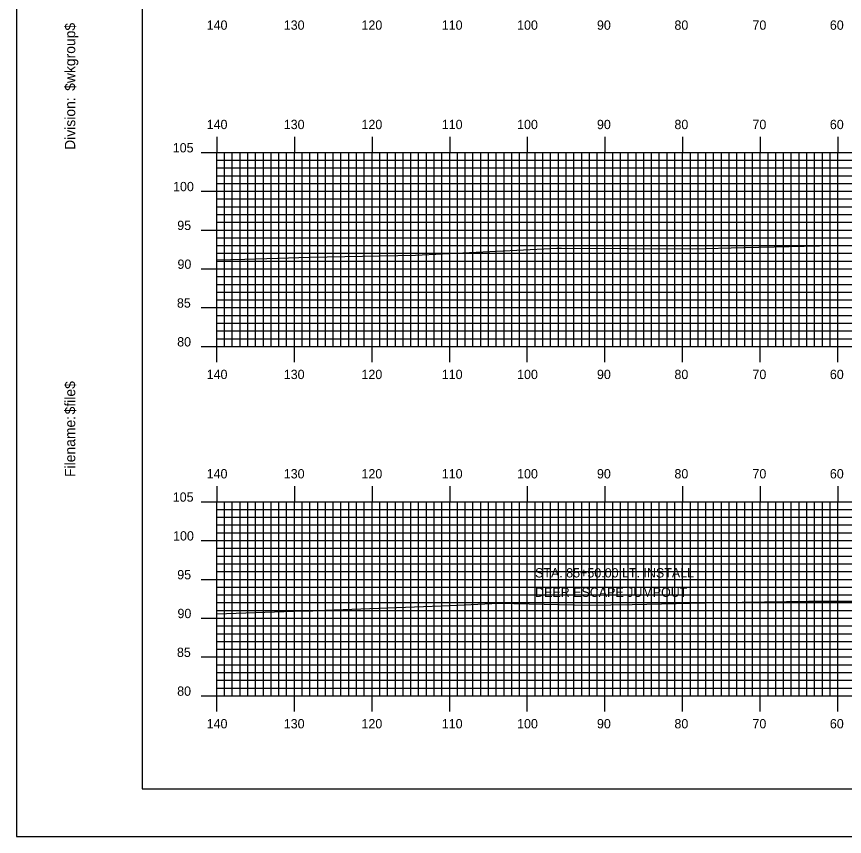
# Model space of a CAD drawing. Extents: x 1763759 to 1764102, y 442591 to 442811.
# Drawn here: x 1763758.5 to 1763865.2, y 442590.5 to 442696.2 of the extents above; entities that cross this region are included whole.
import ezdxf

# ---------------------------------------------------------------- set-up
doc = ezdxf.new("R2010")
doc.units = 0
for name, color, linetype in [('BORDER', 7, 'Continuous'), ('D_Text_Standard', 7, 'Continuous'), ('H_V ANNOTATION', 7, 'Continuous'), ('MAJOR', 7, 'Continuous'), ('MINOR', 7, 'Continuous'), ('PLOT BOUNDARY', 7, 'Continuous'), ('S_Roadway_Centerline', 7, 'Continuous')]:
    doc.layers.add(name, color=color, linetype=linetype)

msp = doc.modelspace()

# ---------------------------------------------------------------- linework, layer by layer
at = {"layer": 'BORDER'}
msp.add_lwpolyline([(1763774.72, 442596.67), (1764094.72, 442596.67), (1764094.72, 442806.67), (1763774.72, 442806.67)], close=True, dxfattribs=at)
at = {"layer": 'MAJOR'}
for p, q in [((1763784.32, 442680.67), (1763784.32, 442678.67)), ((1763794.32, 442680.67), (1763794.32, 442678.67)), ((1763804.32, 442680.67), (1763804.32, 442678.67)), ((1763814.32, 442680.67), (1763814.32, 442678.67)), ((1763824.32, 442680.67), (1763824.32, 442678.67)), ((1763834.32, 442680.67), (1763834.32, 442678.67)), ((1763844.32, 442680.67), (1763844.32, 442678.67)), ((1763854.32, 442680.67), (1763854.32, 442678.67)), ((1763864.32, 442680.67), (1763864.32, 442678.67)), ((1763782.31, 442678.67), (1763784.32, 442678.67)), ((1763784.32, 442678.67), (1764064.32, 442678.67)), ((1763784.32, 442653.67), (1763784.32, 442678.67)), ((1763784.32, 442653.67), (1763784.32, 442678.67)), ((1763784.32, 442678.67), (1764064.32, 442678.67)), ((1763794.32, 442653.67), (1763794.32, 442678.67)), ((1763804.32, 442653.67), (1763804.32, 442678.67)), ((1763814.32, 442653.67), (1763814.32, 442678.67)), ((1763824.32, 442653.67), (1763824.32, 442678.67)), ((1763834.32, 442653.67), (1763834.32, 442678.67)), ((1763844.32, 442653.67), (1763844.32, 442678.67)), ((1763854.32, 442653.67), (1763854.32, 442678.67)), ((1763864.32, 442653.67), (1763864.32, 442678.67)), ((1763782.31, 442673.67), (1763784.32, 442673.67)), ((1763784.32, 442673.67), (1764064.32, 442673.67)), ((1763782.31, 442668.67), (1763784.32, 442668.67)), ((1763784.32, 442668.67), (1764064.32, 442668.67)), ((1763782.31, 442663.67), (1763784.32, 442663.67)), ((1763784.32, 442663.67), (1764064.32, 442663.67)), ((1763782.31, 442658.67), (1763784.32, 442658.67)), ((1763784.32, 442658.67), (1764064.32, 442658.67)), ((1763782.31, 442653.67), (1763784.32, 442653.67)), ((1763784.32, 442653.67), (1764064.32, 442653.67)), ((1763784.32, 442653.67), (1764064.32, 442653.67)), ((1763784.32, 442651.66), (1763784.32, 442653.67)), ((1763794.32, 442651.66), (1763794.32, 442653.67)), ((1763804.32, 442651.66), (1763804.32, 442653.67)), ((1763814.32, 442651.66), (1763814.32, 442653.67)), ((1763824.32, 442651.66), (1763824.32, 442653.67)), ((1763834.32, 442651.66), (1763834.32, 442653.67)), ((1763844.32, 442651.66), (1763844.32, 442653.67)), ((1763854.32, 442651.66), (1763854.32, 442653.67)), ((1763864.32, 442651.66), (1763864.32, 442653.67)), ((1763784.32, 442635.67), (1763784.32, 442633.67)), ((1763794.32, 442635.67), (1763794.32, 442633.67)), ((1763804.32, 442635.67), (1763804.32, 442633.67)), ((1763814.32, 442635.67), (1763814.32, 442633.67)), ((1763824.32, 442635.67), (1763824.32, 442633.67)), ((1763834.32, 442635.67), (1763834.32, 442633.67)), ((1763844.32, 442635.67), (1763844.32, 442633.67)), ((1763854.32, 442635.67), (1763854.32, 442633.67)), ((1763864.32, 442635.67), (1763864.32, 442633.67)), ((1763782.31, 442633.67), (1763784.32, 442633.67)), ((1763784.32, 442633.67), (1764064.32, 442633.67)), ((1763784.32, 442608.67), (1763784.32, 442633.67)), ((1763784.32, 442608.67), (1763784.32, 442633.67)), ((1763784.32, 442633.67), (1764064.32, 442633.67)), ((1763794.32, 442608.67), (1763794.32, 442633.67)), ((1763804.32, 442608.67), (1763804.32, 442633.67)), ((1763814.32, 442608.67), (1763814.32, 442633.67)), ((1763824.32, 442608.67), (1763824.32, 442633.67)), ((1763834.32, 442608.67), (1763834.32, 442633.67)), ((1763844.32, 442608.67), (1763844.32, 442633.67)), ((1763854.32, 442608.67), (1763854.32, 442633.67)), ((1763864.32, 442608.67), (1763864.32, 442633.67)), ((1763782.31, 442628.67), (1763784.32, 442628.67)), ((1763784.32, 442628.67), (1764064.32, 442628.67)), ((1763782.31, 442623.67), (1763784.32, 442623.67)), ((1763784.32, 442623.67), (1764064.32, 442623.67)), ((1763782.31, 442618.67), (1763784.32, 442618.67)), ((1763784.32, 442618.67), (1764064.32, 442618.67)), ((1763782.31, 442613.67), (1763784.32, 442613.67)), ((1763784.32, 442613.67), (1764064.32, 442613.67)), ((1763782.31, 442608.67), (1763784.32, 442608.67)), ((1763784.32, 442608.67), (1764064.32, 442608.67)), ((1763784.32, 442608.67), (1764064.32, 442608.67)), ((1763784.32, 442606.66), (1763784.32, 442608.67)), ((1763794.32, 442606.66), (1763794.32, 442608.67)), ((1763804.32, 442606.66), (1763804.32, 442608.67)), ((1763814.32, 442606.66), (1763814.32, 442608.67)), ((1763824.32, 442606.66), (1763824.32, 442608.67)), ((1763834.32, 442606.66), (1763834.32, 442608.67)), ((1763844.32, 442606.66), (1763844.32, 442608.67)), ((1763854.32, 442606.66), (1763854.32, 442608.67)), ((1763864.32, 442606.66), (1763864.32, 442608.67))]:
    msp.add_line(p, q, dxfattribs=at)
at = {"layer": 'MINOR'}
for p, q in [((1763785.32, 442653.67), (1763785.32, 442678.67)), ((1763786.32, 442653.67), (1763786.32, 442678.67)), ((1763787.32, 442653.67), (1763787.32, 442678.67)), ((1763788.32, 442653.67), (1763788.32, 442678.67)), ((1763789.32, 442653.67), (1763789.32, 442678.67)), ((1763790.32, 442653.67), (1763790.32, 442678.67)), ((1763791.32, 442653.67), (1763791.32, 442678.67)), ((1763792.32, 442653.67), (1763792.32, 442678.67)), ((1763793.32, 442653.67), (1763793.32, 442678.67)), ((1763795.32, 442653.67), (1763795.32, 442678.67)), ((1763796.32, 442653.67), (1763796.32, 442678.67)), ((1763797.32, 442653.67), (1763797.32, 442678.67)), ((1763798.32, 442653.67), (1763798.32, 442678.67)), ((1763799.32, 442653.67), (1763799.32, 442678.67)), ((1763800.32, 442653.67), (1763800.32, 442678.67)), ((1763801.32, 442653.67), (1763801.32, 442678.67)), ((1763802.32, 442653.67), (1763802.32, 442678.67)), ((1763803.32, 442653.67), (1763803.32, 442678.67)), ((1763805.32, 442653.67), (1763805.32, 442678.67)), ((1763806.32, 442653.67), (1763806.32, 442678.67)), ((1763807.32, 442653.67), (1763807.32, 442678.67)), ((1763808.32, 442653.67), (1763808.32, 442678.67)), ((1763809.32, 442653.67), (1763809.32, 442678.67)), ((1763810.32, 442653.67), (1763810.32, 442678.67)), ((1763811.32, 442653.67), (1763811.32, 442678.67)), ((1763812.32, 442653.67), (1763812.32, 442678.67)), ((1763813.32, 442653.67), (1763813.32, 442678.67)), ((1763815.32, 442653.67), (1763815.32, 442678.67)), ((1763816.32, 442653.67), (1763816.32, 442678.67)), ((1763817.32, 442653.67), (1763817.32, 442678.67)), ((1763818.32, 442653.67), (1763818.32, 442678.67)), ((1763819.32, 442653.67), (1763819.32, 442678.67)), ((1763820.32, 442653.67), (1763820.32, 442678.67)), ((1763821.32, 442653.67), (1763821.32, 442678.67)), ((1763822.32, 442653.67), (1763822.32, 442678.67)), ((1763823.32, 442653.67), (1763823.32, 442678.67)), ((1763825.32, 442653.67), (1763825.32, 442678.67)), ((1763826.32, 442653.67), (1763826.32, 442678.67)), ((1763827.32, 442653.67), (1763827.32, 442678.67)), ((1763828.32, 442653.67), (1763828.32, 442678.67)), ((1763829.32, 442653.67), (1763829.32, 442678.67)), ((1763830.32, 442653.67), (1763830.32, 442678.67)), ((1763831.32, 442653.67), (1763831.32, 442678.67)), ((1763832.32, 442653.67), (1763832.32, 442678.67)), ((1763833.32, 442653.67), (1763833.32, 442678.67)), ((1763835.32, 442653.67), (1763835.32, 442678.67)), ((1763836.32, 442653.67), (1763836.32, 442678.67)), ((1763837.32, 442653.67), (1763837.32, 442678.67)), ((1763838.32, 442653.67), (1763838.32, 442678.67)), ((1763839.32, 442653.67), (1763839.32, 442678.67)), ((1763840.32, 442653.67), (1763840.32, 442678.67)), ((1763841.32, 442653.67), (1763841.32, 442678.67)), ((1763842.32, 442653.67), (1763842.32, 442678.67)), ((1763843.32, 442653.67), (1763843.32, 442678.67)), ((1763845.32, 442653.67), (1763845.32, 442678.67)), ((1763846.32, 442653.67), (1763846.32, 442678.67)), ((1763847.32, 442653.67), (1763847.32, 442678.67)), ((1763848.32, 442653.67), (1763848.32, 442678.67)), ((1763849.32, 442653.67), (1763849.32, 442678.67)), ((1763850.32, 442653.67), (1763850.32, 442678.67)), ((1763851.32, 442653.67), (1763851.32, 442678.67)), ((1763852.32, 442653.67), (1763852.32, 442678.67)), ((1763853.32, 442653.67), (1763853.32, 442678.67)), ((1763855.32, 442653.67), (1763855.32, 442678.67)), ((1763856.32, 442653.67), (1763856.32, 442678.67)), ((1763857.32, 442653.67), (1763857.32, 442678.67)), ((1763858.32, 442653.67), (1763858.32, 442678.67)), ((1763859.32, 442653.67), (1763859.32, 442678.67)), ((1763860.32, 442653.67), (1763860.32, 442678.67)), ((1763861.32, 442653.67), (1763861.32, 442678.67)), ((1763862.32, 442653.67), (1763862.32, 442678.67)), ((1763863.32, 442653.67), (1763863.32, 442678.67)), ((1763784.32, 442677.67), (1764064.32, 442677.67)), ((1763784.32, 442677.67), (1763786.32, 442677.67)), ((1763784.32, 442676.67), (1764064.32, 442676.67)), ((1763784.32, 442676.67), (1763786.32, 442676.67)), ((1763784.32, 442675.67), (1764064.32, 442675.67)), ((1763784.32, 442675.67), (1763786.32, 442675.67)), ((1763784.32, 442674.67), (1764064.32, 442674.67)), ((1763784.32, 442674.67), (1763786.32, 442674.67)), ((1763784.32, 442672.67), (1764064.32, 442672.67)), ((1763784.32, 442672.67), (1763786.32, 442672.67)), ((1763784.32, 442671.67), (1764064.32, 442671.67)), ((1763784.32, 442671.67), (1763786.32, 442671.67)), ((1763784.32, 442670.67), (1764064.32, 442670.67)), ((1763784.32, 442670.67), (1763786.32, 442670.67)), ((1763784.32, 442669.67), (1764064.32, 442669.67)), ((1763784.32, 442669.67), (1763786.32, 442669.67)), ((1763784.32, 442667.67), (1764064.32, 442667.67)), ((1763784.32, 442667.67), (1763786.32, 442667.67)), ((1763784.32, 442666.67), (1764064.32, 442666.67)), ((1763784.32, 442666.67), (1763786.32, 442666.67)), ((1763784.32, 442665.67), (1764064.32, 442665.67)), ((1763784.32, 442665.67), (1763786.32, 442665.67)), ((1763784.32, 442664.67), (1764064.32, 442664.67)), ((1763784.32, 442664.67), (1763786.32, 442664.67)), ((1763784.32, 442662.67), (1764064.32, 442662.67)), ((1763784.32, 442662.67), (1763786.32, 442662.67)), ((1763784.32, 442661.67), (1764064.32, 442661.67)), ((1763784.32, 442661.67), (1763786.32, 442661.67)), ((1763784.32, 442660.67), (1764064.32, 442660.67)), ((1763784.32, 442660.67), (1763786.32, 442660.67)), ((1763784.32, 442659.67), (1764064.32, 442659.67)), ((1763784.32, 442659.67), (1763786.32, 442659.67)), ((1763784.32, 442657.67), (1764064.32, 442657.67)), ((1763784.32, 442657.67), (1763786.32, 442657.67)), ((1763784.32, 442656.67), (1764064.32, 442656.67)), ((1763784.32, 442656.67), (1763786.32, 442656.67)), ((1763784.32, 442655.67), (1764064.32, 442655.67)), ((1763784.32, 442655.67), (1763786.32, 442655.67)), ((1763784.32, 442654.67), (1764064.32, 442654.67)), ((1763784.32, 442654.67), (1763786.32, 442654.67)), ((1763785.32, 442608.67), (1763785.32, 442633.67)), ((1763786.32, 442608.67), (1763786.32, 442633.67)), ((1763787.32, 442608.67), (1763787.32, 442633.67)), ((1763788.32, 442608.67), (1763788.32, 442633.67)), ((1763789.32, 442608.67), (1763789.32, 442633.67)), ((1763790.32, 442608.67), (1763790.32, 442633.67)), ((1763791.32, 442608.67), (1763791.32, 442633.67)), ((1763792.32, 442608.67), (1763792.32, 442633.67)), ((1763793.32, 442608.67), (1763793.32, 442633.67)), ((1763795.32, 442608.67), (1763795.32, 442633.67)), ((1763796.32, 442608.67), (1763796.32, 442633.67)), ((1763797.32, 442608.67), (1763797.32, 442633.67)), ((1763798.32, 442608.67), (1763798.32, 442633.67)), ((1763799.32, 442608.67), (1763799.32, 442633.67)), ((1763800.32, 442608.67), (1763800.32, 442633.67)), ((1763801.32, 442608.67), (1763801.32, 442633.67)), ((1763802.32, 442608.67), (1763802.32, 442633.67)), ((1763803.32, 442608.67), (1763803.32, 442633.67)), ((1763805.32, 442608.67), (1763805.32, 442633.67)), ((1763806.32, 442608.67), (1763806.32, 442633.67)), ((1763807.32, 442608.67), (1763807.32, 442633.67)), ((1763808.32, 442608.67), (1763808.32, 442633.67)), ((1763809.32, 442608.67), (1763809.32, 442633.67)), ((1763810.32, 442608.67), (1763810.32, 442633.67)), ((1763811.32, 442608.67), (1763811.32, 442633.67)), ((1763812.32, 442608.67), (1763812.32, 442633.67)), ((1763813.32, 442608.67), (1763813.32, 442633.67)), ((1763815.32, 442608.67), (1763815.32, 442633.67)), ((1763816.32, 442608.67), (1763816.32, 442633.67)), ((1763817.32, 442608.67), (1763817.32, 442633.67)), ((1763818.32, 442608.67), (1763818.32, 442633.67)), ((1763819.32, 442608.67), (1763819.32, 442633.67)), ((1763820.32, 442608.67), (1763820.32, 442633.67)), ((1763821.32, 442608.67), (1763821.32, 442633.67)), ((1763822.32, 442608.67), (1763822.32, 442633.67)), ((1763823.32, 442608.67), (1763823.32, 442633.67)), ((1763825.32, 442608.67), (1763825.32, 442633.67)), ((1763826.32, 442608.67), (1763826.32, 442633.67)), ((1763827.32, 442608.67), (1763827.32, 442633.67)), ((1763828.32, 442608.67), (1763828.32, 442633.67)), ((1763829.32, 442608.67), (1763829.32, 442633.67)), ((1763830.32, 442608.67), (1763830.32, 442633.67)), ((1763831.32, 442608.67), (1763831.32, 442633.67)), ((1763832.32, 442608.67), (1763832.32, 442633.67)), ((1763833.32, 442608.67), (1763833.32, 442633.67)), ((1763835.32, 442608.67), (1763835.32, 442633.67)), ((1763836.32, 442608.67), (1763836.32, 442633.67)), ((1763837.32, 442608.67), (1763837.32, 442633.67)), ((1763838.32, 442608.67), (1763838.32, 442633.67)), ((1763839.32, 442608.67), (1763839.32, 442633.67)), ((1763840.32, 442608.67), (1763840.32, 442633.67)), ((1763841.32, 442608.67), (1763841.32, 442633.67)), ((1763842.32, 442608.67), (1763842.32, 442633.67)), ((1763843.32, 442608.67), (1763843.32, 442633.67)), ((1763845.32, 442608.67), (1763845.32, 442633.67)), ((1763846.32, 442608.67), (1763846.32, 442633.67)), ((1763847.32, 442608.67), (1763847.32, 442633.67)), ((1763848.32, 442608.67), (1763848.32, 442633.67)), ((1763849.32, 442608.67), (1763849.32, 442633.67)), ((1763850.32, 442608.67), (1763850.32, 442633.67)), ((1763851.32, 442608.67), (1763851.32, 442633.67)), ((1763852.32, 442608.67), (1763852.32, 442633.67)), ((1763853.32, 442608.67), (1763853.32, 442633.67)), ((1763855.32, 442608.67), (1763855.32, 442633.67)), ((1763856.32, 442608.67), (1763856.32, 442633.67)), ((1763857.32, 442608.67), (1763857.32, 442633.67)), ((1763858.32, 442608.67), (1763858.32, 442633.67)), ((1763859.32, 442608.67), (1763859.32, 442633.67)), ((1763860.32, 442608.67), (1763860.32, 442633.67)), ((1763861.32, 442608.67), (1763861.32, 442633.67)), ((1763862.32, 442608.67), (1763862.32, 442633.67)), ((1763863.32, 442608.67), (1763863.32, 442633.67)), ((1763784.32, 442632.67), (1764064.32, 442632.67)), ((1763784.32, 442632.67), (1763786.32, 442632.67)), ((1763784.32, 442631.67), (1764064.32, 442631.67)), ((1763784.32, 442631.67), (1763786.32, 442631.67)), ((1763784.32, 442630.67), (1764064.32, 442630.67)), ((1763784.32, 442630.67), (1763786.32, 442630.67)), ((1763784.32, 442629.67), (1764064.32, 442629.67)), ((1763784.32, 442629.67), (1763786.32, 442629.67)), ((1763784.32, 442627.67), (1764064.32, 442627.67)), ((1763784.32, 442627.67), (1763786.32, 442627.67)), ((1763784.32, 442626.67), (1764064.32, 442626.67)), ((1763784.32, 442626.67), (1763786.32, 442626.67)), ((1763784.32, 442625.67), (1764064.32, 442625.67)), ((1763784.32, 442625.67), (1763786.32, 442625.67)), ((1763784.32, 442624.67), (1764064.32, 442624.67)), ((1763784.32, 442624.67), (1763786.32, 442624.67)), ((1763784.32, 442622.67), (1764064.32, 442622.67)), ((1763784.32, 442622.67), (1763786.32, 442622.67)), ((1763784.32, 442621.67), (1764064.32, 442621.67)), ((1763784.32, 442621.67), (1763786.32, 442621.67)), ((1763784.32, 442620.67), (1764064.32, 442620.67)), ((1763784.32, 442620.67), (1763786.32, 442620.67)), ((1763784.32, 442619.67), (1764064.32, 442619.67)), ((1763784.32, 442619.67), (1763786.32, 442619.67)), ((1763784.32, 442617.67), (1764064.32, 442617.67)), ((1763784.32, 442617.67), (1763786.32, 442617.67)), ((1763784.32, 442616.67), (1764064.32, 442616.67)), ((1763784.32, 442616.67), (1763786.32, 442616.67)), ((1763784.32, 442615.67), (1764064.32, 442615.67)), ((1763784.32, 442615.67), (1763786.32, 442615.67)), ((1763784.32, 442614.67), (1764064.32, 442614.67)), ((1763784.32, 442614.67), (1763786.32, 442614.67)), ((1763784.32, 442612.67), (1764064.32, 442612.67)), ((1763784.32, 442612.67), (1763786.32, 442612.67)), ((1763784.32, 442611.67), (1764064.32, 442611.67)), ((1763784.32, 442611.67), (1763786.32, 442611.67)), ((1763784.32, 442610.67), (1764064.32, 442610.67)), ((1763784.32, 442610.67), (1763786.32, 442610.67)), ((1763784.32, 442609.67), (1764064.32, 442609.67)), ((1763784.32, 442609.67), (1763786.32, 442609.67))]:
    msp.add_line(p, q, dxfattribs=at)
at = {"layer": 'PLOT BOUNDARY'}
msp.add_lwpolyline([(1763758.53, 442590.55), (1764098.53, 442590.55), (1764098.53, 442810.55), (1763758.53, 442810.55)], close=True, dxfattribs=at)
at = {"layer": 'S_Roadway_Centerline'}
for points in [[(1763784.32, 442664.81), (1763787.95, 442664.91), (1763792.17, 442665.04), (1763796.27, 442665.18), (1763809.93, 442665.45), (1763827.32, 442666.3), (1763828.13, 442666.32), (1763828.72, 442666.32), (1763845.63, 442666.25), (1763852.2, 442666.42), (1763863.88, 442666.68), (1763865.48, 442666.68)], [(1763784.32, 442619.22), (1763795.47, 442619.61), (1763796.68, 442619.63), (1763797.12, 442619.65), (1763798.3, 442619.71), (1763814.4, 442620.3), (1763820.63, 442620.6), (1763832.32, 442620.33), (1763837.84, 442620.44), (1763849.16, 442620.7), (1763860.52, 442620.85), (1763867.82, 442620.86)]]:
    msp.add_lwpolyline(points, dxfattribs=at)

# ---------------------------------------------------------------- texts
at = {"layer": 'BORDER'}
for s, p in [('$wkgroup$', (1763766.09, 442686.6)), ('Division:', (1763766.09, 442679)), ('$file$', (1763766.09, 442644.92)), ('Filename:', (1763766.09, 442636.86))]:
    msp.add_text(s, height=1.339, rotation=90, dxfattribs=at).set_placement(p)
at = {"layer": 'D_Text_Standard'}
for s, p in [('STA. 85+50.00 LT. INSTALL ', (1763825.32, 442623.91)), ('DEER ESCAPE JUMPOUT', (1763825.32, 442621.41))]:
    msp.add_text(s, height=1.2, dxfattribs=at).set_placement(p)
at = {"layer": 'H_V ANNOTATION'}
for s, p in [('140', (1763783.02, 442694.47)), ('130', (1763792.95, 442694.47)), ('120', (1763802.96, 442694.47)), ('110', (1763813.3, 442694.47)), ('100', (1763823, 442694.47)), ('90', (1763833.29, 442694.47)), ('80', (1763843.27, 442694.47)), ('70', (1763853.32, 442694.47)), ('60', (1763863.29, 442694.47)), ('140', (1763783.02, 442681.67)), ('130', (1763792.95, 442681.67)), ('120', (1763802.96, 442681.67)), ('110', (1763813.3, 442681.67)), ('100', (1763823, 442681.67)), ('90', (1763833.29, 442681.67)), ('80', (1763843.27, 442681.67)), ('70', (1763853.32, 442681.67)), ('60', (1763863.29, 442681.67)), ('105', (1763778.65, 442678.67)), ('100', (1763778.69, 442673.67)), ('95', (1763779.23, 442668.67)), ('90', (1763779.26, 442663.67)), ('85', (1763779.19, 442658.67)), ('80', (1763779.22, 442653.67)), ('140', (1763783.02, 442649.47)), ('130', (1763792.95, 442649.47)), ('120', (1763802.96, 442649.47)), ('110', (1763813.3, 442649.47)), ('100', (1763823, 442649.47)), ('90', (1763833.29, 442649.47)), ('80', (1763843.27, 442649.47)), ('70', (1763853.32, 442649.47)), ('60', (1763863.29, 442649.47)), ('140', (1763783.02, 442636.67)), ('130', (1763792.95, 442636.67)), ('120', (1763802.96, 442636.67)), ('110', (1763813.3, 442636.67)), ('100', (1763823, 442636.67)), ('90', (1763833.29, 442636.67)), ('80', (1763843.27, 442636.67)), ('70', (1763853.32, 442636.67)), ('60', (1763863.29, 442636.67)), ('105', (1763778.65, 442633.67)), ('100', (1763778.69, 442628.67)), ('95', (1763779.23, 442623.67)), ('90', (1763779.26, 442618.67)), ('85', (1763779.19, 442613.67)), ('80', (1763779.22, 442608.67)), ('140', (1763783.02, 442604.47)), ('130', (1763792.95, 442604.47)), ('120', (1763802.96, 442604.47)), ('110', (1763813.3, 442604.47)), ('100', (1763823, 442604.47)), ('90', (1763833.29, 442604.47)), ('80', (1763843.27, 442604.47)), ('70', (1763853.32, 442604.47)), ('60', (1763863.29, 442604.47))]:
    msp.add_text(s, height=1.2, dxfattribs=at).set_placement(p)
at = {"layer": 'MAJOR'}
for p in [(1763784.31, 442653.67), (1763784.31, 442608.67)]:
    msp.add_text('-', height=0.012, dxfattribs=at).set_placement(p)

doc.saveas('drawing.dxf')
